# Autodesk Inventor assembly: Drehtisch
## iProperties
Shininess: 64.0
Length Units: 11269
Angle Units: 11279
Time Units: 11290
Mass Units: 11283
Length Display Precision: 3
Angle Display Precision: 2
Compacted: True
Created: 2004-01
Part Number: Drehtisch
Document SubType Name: Assembly
Designer: chefe
Manufacturer: Standard
Standards Organization: Custom
Density: 0.0
Volumn: 0.0
Area: 0.0
PropertySet Name: Model Information
Control State: 0
Master: False
Checked Out: False
Author: chefe
